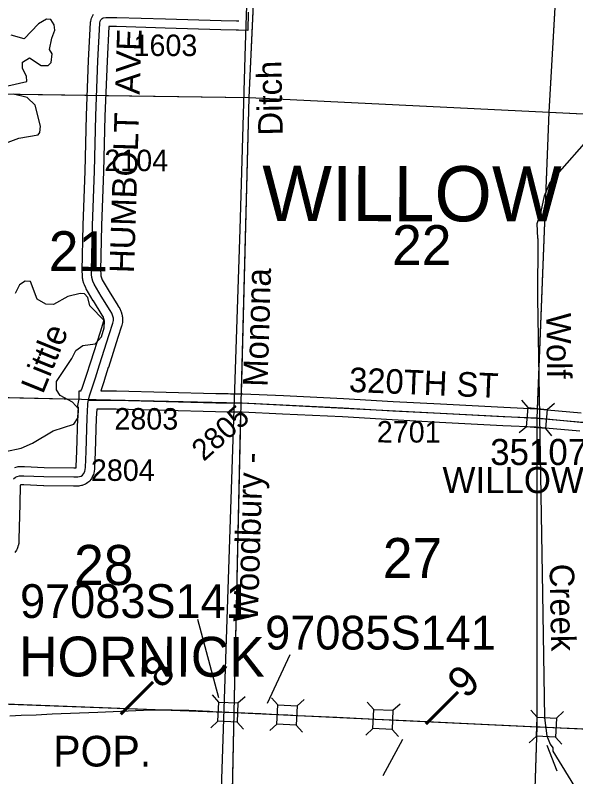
# Model space of a CAD drawing. Extents: x -157.2 to -99.3, y 12.2 to 46.2.
# Drawn here: x -132.874 to -131.046, y 17.437 to 19.92 of the extents above; entities that cross this region are included whole.
import ezdxf

# ---------------------------------------------------------------- set-up
doc = ezdxf.new("R2010")
doc.units = 0
for name, color, linetype in [('tdCoCorpPopTxt', 7, 'Continuous'), ('tdCoCorpTxt', 7, 'Continuous'), ('tdCoHydroRiver', 7, 'Continuous'), ('tdCoHydroTxtLg', 7, 'Continuous'), ('tdCoPriCL', 7, 'Continuous'), ('tdCoPriNonDiv', 7, 'Continuous'), ('tdCoPriNonDivCL', 7, 'Continuous'), ('tdCoSecRdNmbr', 7, 'Continuous'), ('tdCoSecRdTxt', 7, 'Continuous'), ('tdCoSecRteBand', 7, 'Continuous'), ('tdCoSecRteCL', 7, 'Continuous'), ('tdCoSectLine', 7, 'Continuous'), ('tdCoSectLinePart', 7, 'Continuous'), ('tdCoSectNmbr', 7, 'Continuous'), ('tdCoStrucNonDivPri', 7, 'Continuous'), ('tdCoStrucPriMaintName', 7, 'Continuous'), ('tdCoStrucSec', 7, 'Continuous'), ('tdCoStrucSecCoName', 7, 'Continuous'), ('tdCoStrucSecFHWANum', 7, 'Continuous'), ('tdCoSurfGravel', 7, 'Continuous'), ('tdCoSurfLNO', 7, 'Continuous'), ('tdCoTwpNameTxt', 7, 'Continuous'), ('tdStHwyPriRefPost1', 7, 'Continuous')]:
    doc.layers.add(name, color=color, linetype=linetype)

msp = doc.modelspace()

# ---------------------------------------------------------------- linework, layer by layer
at = {"layer": 'tdCoHydroRiver'}
for points in [[(-132.1226, 19.8224), (-132.1017, 20.4678)], [(-131.1696, 19.1917), (-131.1723, 19.2409), (-131.1585, 19.2799), (-131.1475, 19.3317), (-131.1304, 19.3739), (-130.9768, 19.5477), (-130.8922, 19.6336), (-130.8854, 19.6492), (-130.8697, 19.9109), (-130.8569, 20.1268)], [(-132.8984, 19.6895), (-132.8364, 19.7035), (-132.8375, 19.7209), (-132.8509, 19.7465), (-132.8503, 19.7671), (-132.8278, 19.7806), (-132.7891, 19.7557), (-132.767, 19.7566), (-132.7572, 19.7658), (-132.7532, 19.7941), (-132.7623, 19.8086), (-132.7549, 19.8447), (-132.7446, 19.8713), (-132.7472, 19.8887), (-132.7578, 19.9064), (-132.772, 19.9068), (-132.7977, 19.8918), (-132.8449, 19.8427), (-132.8872, 19.855)], [(-132.1404, 19.2211), (-132.1226, 19.8224)], [(-132.8975, 19.5063), (-132.8624, 19.5195), (-132.7989, 19.5302), (-132.794, 19.5379), (-132.7918, 19.5584), (-132.8087, 19.6268), (-132.8348, 19.6513), (-132.8803, 19.6621)], [(-132.2292, 16.5498), (-132.1404, 19.2211)], [(-131.1696, 19.1917), (-131.1706, 18.9975), (-131.1548, 18.0351), (-131.1479, 17.6289), (-131.1402, 17.5702), (-131.1299, 17.5431), (-131.1208, 17.5318), (-131.1211, 17.5207), (-131.0201, 17.3581), (-130.8557, 17.1036), (-130.8545, 17.0925), (-130.8001, 17.0118), (-130.7907, 17.0084)], [(-132.9054, 18.4973), (-132.8546, 18.5083), (-132.8178, 18.5246), (-132.7503, 18.5652), (-132.6833, 18.5869), (-132.6685, 18.6085), (-132.6676, 18.6369), (-132.6875, 18.6581), (-132.7279, 18.6798), (-132.7399, 18.6991), (-132.7391, 18.726), (-132.6895, 18.8003), (-132.6761, 18.8267), (-132.6535, 18.8434), (-132.6139, 18.8485), (-132.5927, 18.8716), (-132.5839, 18.9013), (-132.5832, 18.9234), (-132.6307, 18.9722), (-132.6378, 18.9993), (-132.6485, 19.0122), (-132.6626, 19.0127), (-132.7024, 19.0028), (-132.7489, 18.9774), (-132.7742, 18.9782), (-132.8021, 18.9948), (-132.8241, 19.0523), (-132.8414, 19.0528), (-132.8607, 19.0408), (-132.8742, 19.0128)]]:
    msp.add_lwpolyline(points, dxfattribs=at)
at = {"layer": 'tdCoPriCL'}
msp.add_lwpolyline([(-132.8919, 17.6361), (-132.8549, 17.6375), (-132.8061, 17.6395), (-132.7535, 17.642), (-132.6046, 17.6476), (-132.4554, 17.6538), (-132.408, 17.655), (-132.3881, 17.655), (-132.3619, 17.655), (-132.3084, 17.6541), (-132.2405, 17.6509), (-132.2297, 17.6504), (-132.2006, 17.649), (-132.1799, 17.648), (-132.16, 17.6471), (-132.0728, 17.6431), (-132.0386, 17.6415), (-131.9899, 17.6388), (-131.9874, 17.6387), (-131.9852, 17.6386), (-131.9526, 17.6368), (-131.8256, 17.6314), (-131.6988, 17.6252), (-131.6773, 17.6242), (-131.6726, 17.624), (-131.5994, 17.6205), (-131.4199, 17.6124), (-131.1901, 17.601), (-131.1717, 17.6002), (-131.162, 17.5997), (-131.1416, 17.5988), (-131.1212, 17.5978), (-130.9792, 17.5912)], dxfattribs=at)
at = {"layer": 'tdCoPriNonDiv'}
msp.add_lwpolyline([(-132.8919, 17.6361), (-132.8549, 17.6375), (-132.8061, 17.6395), (-132.7535, 17.642), (-132.6046, 17.6476), (-132.4554, 17.6538), (-132.408, 17.655), (-132.3619, 17.655), (-132.3084, 17.6541), (-132.2405, 17.6509), (-132.2297, 17.6504), (-132.0728, 17.6431), (-132.0386, 17.6415), (-131.9899, 17.6388), (-131.9526, 17.6368), (-131.8256, 17.6314), (-131.6988, 17.6252), (-131.6773, 17.6242), (-131.5994, 17.6205), (-131.4199, 17.6124), (-131.1901, 17.601), (-131.162, 17.5997), (-130.9792, 17.5912)], dxfattribs=at)
at = {"layer": 'tdCoPriNonDivCL'}
msp.add_lwpolyline([(-132.8919, 17.6361), (-132.8549, 17.6375), (-132.8061, 17.6395), (-132.7535, 17.642), (-132.6046, 17.6476), (-132.4554, 17.6538), (-132.408, 17.655), (-132.3881, 17.655), (-132.3619, 17.655), (-132.3084, 17.6541), (-132.2297, 17.6504), (-132.0728, 17.6431), (-132.0386, 17.6415), (-131.9526, 17.6368), (-131.8256, 17.6314), (-131.6988, 17.6252), (-131.5994, 17.6205), (-131.4199, 17.6124), (-131.1901, 17.601), (-130.9792, 17.5912)], dxfattribs=at)
msp.add_lwpolyline([(-132.8919, 17.6361), (-132.8549, 17.6375), (-132.8061, 17.6395), (-132.7535, 17.642), (-132.6046, 17.6476), (-132.4554, 17.6538), (-132.408, 17.655), (-132.3881, 17.655), (-132.3619, 17.655), (-132.3084, 17.6541), (-132.2297, 17.6504), (-132.0728, 17.6431), (-132.0386, 17.6415), (-131.9526, 17.6368), (-131.8256, 17.6314), (-131.6988, 17.6252), (-131.5994, 17.6205), (-131.4199, 17.6124), (-131.1901, 17.601), (-130.9792, 17.5912)], dxfattribs=at)
at = {"layer": 'tdCoSecRteBand'}
for points in [[(-132.8759, 18.445), (-132.8683, 18.4472), (-132.8644, 18.4483), (-132.8604, 18.4484), (-132.8461, 18.4486), (-132.8453, 18.4487), (-132.8444, 18.4486), (-132.7795, 18.4459), (-132.6827, 18.4447), (-132.6826, 18.4447), (-132.6826, 18.4447), (-132.6759, 18.4446), (-132.6753, 18.4485), (-132.6729, 18.4985), (-132.6697, 18.6079), (-132.6697, 18.6082), (-132.6697, 18.6084), (-132.6682, 18.642), (-132.6713, 18.6428), (-132.6652, 18.6685), (-132.6653, 18.695), (-132.659, 18.695), (-132.6576, 18.7012), (-132.6564, 18.7009), (-132.6414, 18.747), (-132.6276, 18.7898), (-132.5963, 18.8879), (-132.5963, 18.8879), (-132.5963, 18.888), (-132.5848, 18.9236), (-132.584, 18.9275), (-132.584, 18.928), (-132.5846, 18.9306), (-132.5863, 18.9351), (-132.5903, 18.9418), (-132.6193, 18.9885), (-132.6195, 18.9888), (-132.6197, 18.9892), (-132.6427, 19.0284), (-132.6435, 19.0298), (-132.6441, 19.0312), (-132.6486, 19.0411), (-132.6495, 19.0431), (-132.6501, 19.0453), (-132.6533, 19.0566), (-132.6541, 19.0595), (-132.6543, 19.0626), (-132.6551, 19.0727), (-132.6551, 19.0732), (-132.6551, 19.0736), (-132.6556, 19.0857), (-132.6557, 19.0867), (-132.6556, 19.0877), (-132.6522, 19.2356), (-132.6522, 19.2358), (-132.6522, 19.236), (-132.646, 19.4121), (-132.6416, 19.593), (-132.6416, 19.5932), (-132.6416, 19.5934), (-132.6347, 19.7722), (-132.6347, 19.7724), (-132.6346, 19.7726), (-132.6282, 19.8959), (-132.6281, 19.898), (-132.6277, 19.9), (-132.6265, 19.9064), (-132.6257, 19.9108), (-132.6236, 19.9147), (-132.6211, 19.9194), (-132.619, 19.9234)], [(-132.114, 19.9305), (-132.1155, 19.8705), (-132.1455, 19.8713), (-132.1536, 19.8715), (-132.2035, 19.8727), (-132.2036, 19.8727), (-132.2036, 19.8727), (-132.3849, 19.8782), (-132.3849, 19.8782), (-132.3849, 19.8782), (-132.5435, 19.8831), (-132.5688, 19.8831), (-132.5747, 19.7697), (-132.5816, 19.5913), (-132.586, 19.4105), (-132.586, 19.4103), (-132.5861, 19.4102), (-132.5922, 19.234), (-132.5956, 19.0872), (-132.5952, 19.0766), (-132.5947, 19.07), (-132.5929, 19.0637), (-132.5901, 19.0573), (-132.5681, 19.0198), (-132.5393, 18.9733), (-132.5392, 18.9732), (-132.5391, 18.973), (-132.5334, 18.9636), (-132.5319, 18.9611), (-132.5308, 18.9583), (-132.5276, 18.9494), (-132.5271, 18.9479), (-132.5267, 18.9463), (-132.525, 18.9391), (-132.5243, 18.9361), (-132.5242, 18.9331), (-132.5239, 18.9257), (-132.5238, 18.9219), (-132.5246, 18.9182), (-132.5266, 18.9093), (-132.5269, 18.908), (-132.5273, 18.9067), (-132.5391, 18.8697), (-132.5704, 18.7715), (-132.5704, 18.7715), (-132.5705, 18.7715), (-132.5843, 18.7286), (-132.5843, 18.7285), (-132.5843, 18.7285), (-132.5952, 18.6952), (-132.5446, 18.6953), (-132.5441, 18.6953), (-132.5437, 18.6953), (-132.2197, 18.6864), (-132.1801, 18.6862), (-132.1716, 18.6861), (-132.1716, 18.6861), (-132.1416, 18.686), (-132.1335, 18.6859), (-132.1329, 18.6859), (-132.1323, 18.6859), (-131.9996, 18.6797), (-131.9996, 18.6797), (-131.9996, 18.6797), (-131.8035, 18.6704), (-131.8033, 18.6704), (-131.8031, 18.6704), (-131.6412, 18.6605), (-131.487, 18.6526), (-131.487, 18.6526), (-131.487, 18.6526), (-131.2809, 18.6418), (-131.173, 18.6368), (-131.1723, 18.6368), (-131.1717, 18.6367), (-131.1391, 18.6338), (-131.139, 18.6338), (-131.139, 18.6338), (-131.028, 18.6232)], [(-131.0329, 18.5634), (-131.1446, 18.574), (-131.1764, 18.5769), (-131.2838, 18.5818), (-131.2839, 18.5818), (-131.284, 18.5818), (-131.4901, 18.5927), (-131.6445, 18.6006), (-131.6446, 18.6006), (-131.6447, 18.6006), (-131.8066, 18.6105), (-132.0024, 18.6198), (-132.1344, 18.6259), (-132.1419, 18.626), (-132.1505, 18.626), (-132.1505, 18.626), (-132.1805, 18.6262), (-132.2204, 18.6264), (-132.2207, 18.6264), (-132.221, 18.6264), (-132.5449, 18.6353), (-132.6084, 18.6352), (-132.6097, 18.6059), (-132.6129, 18.4964), (-132.6129, 18.4962), (-132.6129, 18.4959), (-132.6154, 18.4439), (-132.6155, 18.442), (-132.6158, 18.4403), (-132.618, 18.4272), (-132.6187, 18.423), (-132.6206, 18.4192), (-132.624, 18.412), (-132.6254, 18.4092), (-132.6274, 18.4066), (-132.6308, 18.4022), (-132.6336, 18.3987), (-132.6372, 18.3961), (-132.6414, 18.3932), (-132.6447, 18.3908), (-132.6484, 18.3895), (-132.6539, 18.3875), (-132.6556, 18.3869), (-132.6575, 18.3864), (-132.6629, 18.3852), (-132.6664, 18.3844), (-132.6701, 18.3845), (-132.6836, 18.3847), (-132.7807, 18.3859), (-132.7811, 18.3859), (-132.7815, 18.386), (-132.846, 18.3886), (-132.8554, 18.3885), (-132.8571, 18.388), (-132.8575, 18.3878), (-132.8579, 18.3875), (-132.8595, 18.3254), (-132.862, 18.212), (-132.862, 18.2045), (-132.862, 18.2008), (-132.8629, 18.1972), (-132.8646, 18.1903), (-132.8651, 18.1885), (-132.8657, 18.1868), (-132.8682, 18.1804), (-132.8691, 18.1779), (-132.8705, 18.1757), (-132.8749, 18.1683)]]:
    msp.add_lwpolyline(points, dxfattribs=at)
at = {"layer": 'tdCoSecRteCL'}
for points in [[(-132.6352, 18.6651), (-132.6318, 18.6796), (-132.6128, 18.7378), (-132.599, 18.7807), (-132.5677, 18.8788), (-132.5559, 18.9158), (-132.5539, 18.9247), (-132.5541, 18.9321), (-132.5559, 18.9392), (-132.5591, 18.9481), (-132.5647, 18.9575), (-132.5938, 19.0043), (-132.6168, 19.0435), (-132.6212, 19.0534), (-132.6244, 19.0648), (-132.6252, 19.0749), (-132.6257, 19.087), (-132.6222, 19.2349), (-132.616, 19.4112), (-132.6116, 19.5922), (-132.6047, 19.771), (-132.5983, 19.8943), (-132.597, 19.9008), (-132.5946, 19.9054), (-132.5911, 19.9089), (-132.5872, 19.9111), (-132.5781, 19.9131), (-132.543, 19.9131), (-132.384, 19.9082), (-132.2027, 19.9027), (-132.1528, 19.9015), (-132.1448, 19.9012)], [(-132.8801, 18.4083), (-132.873, 18.4137), (-132.8676, 18.4162), (-132.8599, 18.4184), (-132.8456, 18.4186), (-132.7803, 18.4159), (-132.6831, 18.4147), (-132.6695, 18.4145), (-132.6641, 18.4157), (-132.6587, 18.4177), (-132.6545, 18.4206), (-132.6511, 18.4251), (-132.6476, 18.4322), (-132.6454, 18.4453), (-132.6429, 18.4973), (-132.6397, 18.6071), (-132.6377, 18.651), (-132.6358, 18.6628), (-132.6352, 18.6651)], [(-132.6352, 18.6651), (-132.5445, 18.6653), (-132.2202, 18.6564), (-132.1803, 18.6562)], [(-132.1418, 18.656), (-132.1337, 18.6559), (-132.001, 18.6498), (-131.8049, 18.6404), (-131.6429, 18.6305), (-131.4885, 18.6227), (-131.2824, 18.6118), (-131.1744, 18.6069), (-131.1418, 18.6039), (-131.0301, 18.5933), (-130.857, 18.5859), (-130.7085, 18.5788), (-130.6311, 18.5753), (-130.5179, 18.5709), (-130.384, 18.5632), (-130.2481, 18.5568), (-130.1635, 18.5526), (-130.1451, 18.553)]]:
    msp.add_lwpolyline(points, dxfattribs=at)
at = {"layer": 'tdCoSectLine'}
for points in [[(-132.1112, 19.6513), (-132.0645, 20.6627)], [(-131.1331, 19.6035), (-131.0741, 20.6295)], [(-133.107, 19.6664), (-132.1112, 19.6513)], [(-132.1373, 18.656), (-132.1112, 19.6513)], [(-132.1112, 19.6513), (-131.1331, 19.6035)], [(-131.1721, 18.6066), (-131.1331, 19.6035)], [(-131.1331, 19.6035), (-130.1367, 19.5555)], [(-133.1316, 18.6788), (-132.1373, 18.656)], [(-132.16, 17.6471), (-132.1373, 18.656)], [(-132.1373, 18.656), (-131.1721, 18.6066)], [(-131.1721, 18.6066), (-131.0355, 18.5938), (-130.1455, 18.553)], [(-131.1717, 17.6002), (-131.1721, 18.6066)], [(-133.1595, 17.684), (-132.16, 17.6471)], [(-132.1802, 16.6753), (-132.16, 17.6471)], [(-132.16, 17.6471), (-131.1717, 17.6002)], [(-131.2035, 16.6296), (-131.1717, 17.6002)], [(-131.1717, 17.6002), (-130.1788, 17.5591)]]:
    msp.add_lwpolyline(points, dxfattribs=at)
at = {"layer": 'tdCoSectLinePart'}
for points in [[(-132.1112, 19.6513), (-132.0734, 20.4687)], [(-131.1331, 19.6035), (-131.0927, 20.3063)], [(-133.077, 19.6659), (-132.6394, 19.6593)], [(-132.5794, 19.6584), (-132.1112, 19.6513)], [(-132.1365, 18.6859), (-132.1112, 19.6513)], [(-132.1112, 19.6513), (-131.1331, 19.6035)], [(-131.171, 18.6366), (-131.1331, 19.6035)], [(-131.1331, 19.6035), (-130.4404, 19.5701)], [(-133.1023, 18.6781), (-132.6655, 18.6681)], [(-132.16, 17.6471), (-132.138, 18.626)], [(-131.1717, 17.6002), (-131.1721, 18.5765)], [(-132.905, 17.6746), (-132.16, 17.6471)], [(-132.1796, 16.7031), (-132.16, 17.6471)], [(-132.16, 17.6471), (-131.1717, 17.6002)], [(-131.2025, 16.6596), (-131.1717, 17.6002)], [(-131.1717, 17.6002), (-130.1788, 17.5591)]]:
    msp.add_lwpolyline(points, dxfattribs=at)
at = {"layer": 'tdCoStrucNonDivPri'}
for p, q in [((-132.2101, 17.6808), (-132.2312, 17.7039)), ((-132.1476, 17.6779), (-132.1244, 17.699)), ((-132.0171, 17.6717), (-132.038, 17.695)), ((-131.9546, 17.6683), (-131.9313, 17.6892)), ((-131.7048, 17.6568), (-131.7258, 17.68)), ((-131.6422, 17.6539), (-131.6191, 17.6749)), ((-131.1714, 17.6315), (-131.1925, 17.6546)), ((-131.1089, 17.6286), (-131.0858, 17.6497)), ((-132.213, 17.6182), (-132.2361, 17.5972)), ((-132.1505, 17.6153), (-132.1294, 17.5922)), ((-132.0205, 17.6091), (-132.0438, 17.5883)), ((-131.958, 17.6057), (-131.9371, 17.5824)), ((-131.7077, 17.5943), (-131.7309, 17.5732)), ((-131.6452, 17.5913), (-131.6241, 17.5682)), ((-131.1744, 17.569), (-131.1975, 17.5479)), ((-131.1118, 17.566), (-131.0908, 17.5429))]:
    msp.add_line(p, q, dxfattribs=at)
for points in [[(-132.2101, 17.6808), (-132.1476, 17.6779), (-132.1505, 17.6153), (-132.213, 17.6182)], [(-132.0171, 17.6717), (-131.9546, 17.6683), (-131.958, 17.6057), (-132.0205, 17.6091)], [(-131.7048, 17.6568), (-131.6422, 17.6539), (-131.6452, 17.5913), (-131.7077, 17.5943)], [(-131.1714, 17.6315), (-131.1089, 17.6286), (-131.1118, 17.566), (-131.1744, 17.569)]]:
    msp.add_lwpolyline(points, close=True, dxfattribs=at)
at = {"layer": 'tdCoStrucPriMaintName'}
for p, q in [((-132.2794, 17.9513), (-132.211, 17.6958)), ((-131.9785, 17.8344), (-132.052, 17.6759)), ((-131.6736, 17.4411), (-131.6097, 17.5595)), ((-131.1061, 17.4555), (-131.1393, 17.5396))]:
    msp.add_line(p, q, dxfattribs=at)
at = {"layer": 'tdCoStrucSec'}
for p, q in [((-131.2013, 18.6407), (-131.2213, 18.6648)), ((-131.139, 18.635), (-131.1149, 18.6551)), ((-131.207, 18.5784), (-131.231, 18.5583)), ((-131.1446, 18.5727), (-131.1246, 18.5487)), ((-132.2101, 17.6808), (-132.2312, 17.7039)), ((-132.1476, 17.6779), (-132.1244, 17.699)), ((-132.0171, 17.6717), (-132.038, 17.695)), ((-131.9546, 17.6683), (-131.9313, 17.6892)), ((-131.7048, 17.6568), (-131.7258, 17.68)), ((-131.6422, 17.6539), (-131.6191, 17.6749)), ((-131.1714, 17.6315), (-131.1925, 17.6546)), ((-131.1089, 17.6286), (-131.0858, 17.6497)), ((-132.213, 17.6182), (-132.2361, 17.5972)), ((-132.1505, 17.6153), (-132.1294, 17.5922)), ((-132.0205, 17.6091), (-132.0438, 17.5883)), ((-131.958, 17.6057), (-131.9371, 17.5824)), ((-131.7077, 17.5943), (-131.7309, 17.5732)), ((-131.6452, 17.5913), (-131.6241, 17.5682)), ((-131.1744, 17.569), (-131.1975, 17.5479)), ((-131.1118, 17.566), (-131.0908, 17.5429))]:
    msp.add_line(p, q, dxfattribs=at)
for points in [[(-131.2013, 18.6407), (-131.139, 18.635), (-131.1446, 18.5727), (-131.207, 18.5784)], [(-132.2101, 17.6808), (-132.1476, 17.6779), (-132.1505, 17.6153), (-132.213, 17.6182)], [(-132.0171, 17.6717), (-131.9546, 17.6683), (-131.958, 17.6057), (-132.0205, 17.6091)], [(-131.7048, 17.6568), (-131.6422, 17.6539), (-131.6452, 17.5913), (-131.7077, 17.5943)], [(-131.1714, 17.6315), (-131.1089, 17.6286), (-131.1118, 17.566), (-131.1744, 17.569)]]:
    msp.add_lwpolyline(points, close=True, dxfattribs=at)
at = {"layer": 'tdCoSurfGravel'}
msp.add_line((-132.1528, 19.9015), (-132.1448, 19.9012), dxfattribs=at)
for points in [[(-132.6352, 18.6651), (-132.6318, 18.6796), (-132.6128, 18.7378), (-132.599, 18.7807), (-132.5677, 18.8788), (-132.5559, 18.9158), (-132.5539, 18.9247), (-132.5541, 18.9321), (-132.5559, 18.9392), (-132.5591, 18.9481), (-132.5647, 18.9575), (-132.5938, 19.0043), (-132.6168, 19.0435), (-132.6212, 19.0534), (-132.6244, 19.0648), (-132.6252, 19.0749), (-132.6257, 19.087), (-132.6222, 19.2349), (-132.616, 19.4112), (-132.6116, 19.5922), (-132.6047, 19.771), (-132.5983, 19.8943), (-132.597, 19.9008), (-132.5946, 19.9054), (-132.5911, 19.9089), (-132.5872, 19.9111), (-132.5781, 19.9131), (-132.543, 19.9131), (-132.384, 19.9082), (-132.2027, 19.9027), (-132.1528, 19.9015)], [(-132.8801, 18.4083), (-132.873, 18.4137), (-132.8676, 18.4162), (-132.8599, 18.4184), (-132.8456, 18.4186), (-132.7803, 18.4159), (-132.6831, 18.4147), (-132.6695, 18.4145), (-132.6641, 18.4157), (-132.6587, 18.4177), (-132.6545, 18.4206), (-132.6511, 18.4251), (-132.6476, 18.4322), (-132.6454, 18.4453), (-132.6429, 18.4973), (-132.6397, 18.6071), (-132.6377, 18.651), (-132.6358, 18.6628), (-132.6352, 18.6651)], [(-132.6352, 18.6651), (-132.5445, 18.6653), (-132.2202, 18.6564), (-132.1803, 18.6562)], [(-132.1418, 18.656), (-132.1337, 18.6559), (-132.001, 18.6498), (-131.8049, 18.6404), (-131.6429, 18.6305), (-131.4885, 18.6227), (-131.2824, 18.6118), (-131.1744, 18.6069), (-131.1418, 18.6039), (-131.0301, 18.5933), (-130.857, 18.5859), (-130.7085, 18.5788), (-130.6311, 18.5753), (-130.5179, 18.5709), (-130.384, 18.5632), (-130.2481, 18.5568), (-130.1635, 18.5526), (-130.1451, 18.553)]]:
    msp.add_lwpolyline(points, dxfattribs=at)
at = {"layer": 'tdCoSurfLNO'}
msp.add_line((-132.1803, 18.6562), (-132.1418, 18.656), dxfattribs=at)

# ---------------------------------------------------------------- texts
at = {"layer": 'tdCoCorpPopTxt'}
msp.add_text('POP.', height=0.1, dxfattribs=at).set_placement((-132.7502, 17.4706))
at = {"layer": 'tdCoCorpTxt'}
msp.add_text('HORNICK', height=0.13, rotation=359.8997, dxfattribs=at).set_placement((-132.8618, 17.7645))
at = {"layer": 'tdCoHydroTxtLg'}
for s, rotation, p in [('Ditch', 91.2364, (-132.0013, 19.5285)), ('Monona', 88.2361, (-132.0515, 18.7078)), ('Wolf', 270.6221, (-131.142, 18.949)), ('Little', 67.9983, (-132.7839, 18.682)), ('Woodbury -', 88.2361, (-132.083, 17.9408)), ('Creek', 271.1093, (-131.1314, 18.1309))]:
    msp.add_text(s, height=0.08, rotation=rotation, dxfattribs=at).set_placement(p)
at = {"layer": 'tdCoSecRdNmbr'}
for s, rotation, p in [('1603', 359.8997, (-132.4884, 19.7871)), ('2104', 359.8996, (-132.5835, 19.4118)), ('2805', 41.8897, (-132.2594, 18.4631)), ('2803', 359.8998, (-132.5507, 18.5693)), ('2701', 359.9004, (-131.6949, 18.527)), ('2804', 359.8997, (-132.6274, 18.4019))]:
    msp.add_text(s, height=0.07, rotation=rotation, dxfattribs=at).set_placement(p)
at = {"layer": 'tdCoSecRdTxt'}
for s, height, rotation, p in [('HUMBOLT  AVE', 0.08, 88.1852, (-132.4868, 19.0783)), ('320TH ST', 0.08, 357.6693, (-131.7868, 18.6921)), ('28', 0.13047, 359.8996, (-132.6823, 18.0626))]:
    msp.add_text(s, height=height, rotation=rotation, dxfattribs=at).set_placement(p)
at = {"layer": 'tdCoSectNmbr'}
for s, rotation, p in [('21', 359.8996, (-132.7647, 19.0858)), ('22', 359.9003, (-131.6448, 19.1058)), ('27', 359.9003, (-131.6752, 18.0856))]:
    msp.add_text(s, height=0.13, rotation=rotation, dxfattribs=at).set_placement(p)
at = {"layer": 'tdCoStrucPriMaintName'}
for s, p in [('97083S141', (-132.8585, 17.955)), ('97085S141', (-132.059, 17.852))]:
    msp.add_text(s, height=0.11, dxfattribs=at).set_placement(p)
at = {"layer": 'tdCoStrucSecCoName'}
msp.add_text('WILLOW U-51', height=0.085, dxfattribs=at).set_placement((-131.4805, 18.362))
at = {"layer": 'tdCoStrucSecFHWANum'}
msp.add_text('351071', height=0.085, dxfattribs=at).set_placement((-131.3249, 18.4535))
at = {"layer": 'tdCoTwpNameTxt'}
msp.add_text('WILLOW', height=0.18, rotation=359.8901, dxfattribs=at).set_placement((-132.0686, 19.2493))
at = {"layer": 'tdStHwyPriRefPost1'}
for s, p in [('‒‒8', (-132.5039, 17.615)), ('‒‒9', (-131.5086, 17.5827))]:
    msp.add_text(s, height=0.1, rotation=45, dxfattribs=at).set_placement(p)

doc.saveas('drawing.dxf')
